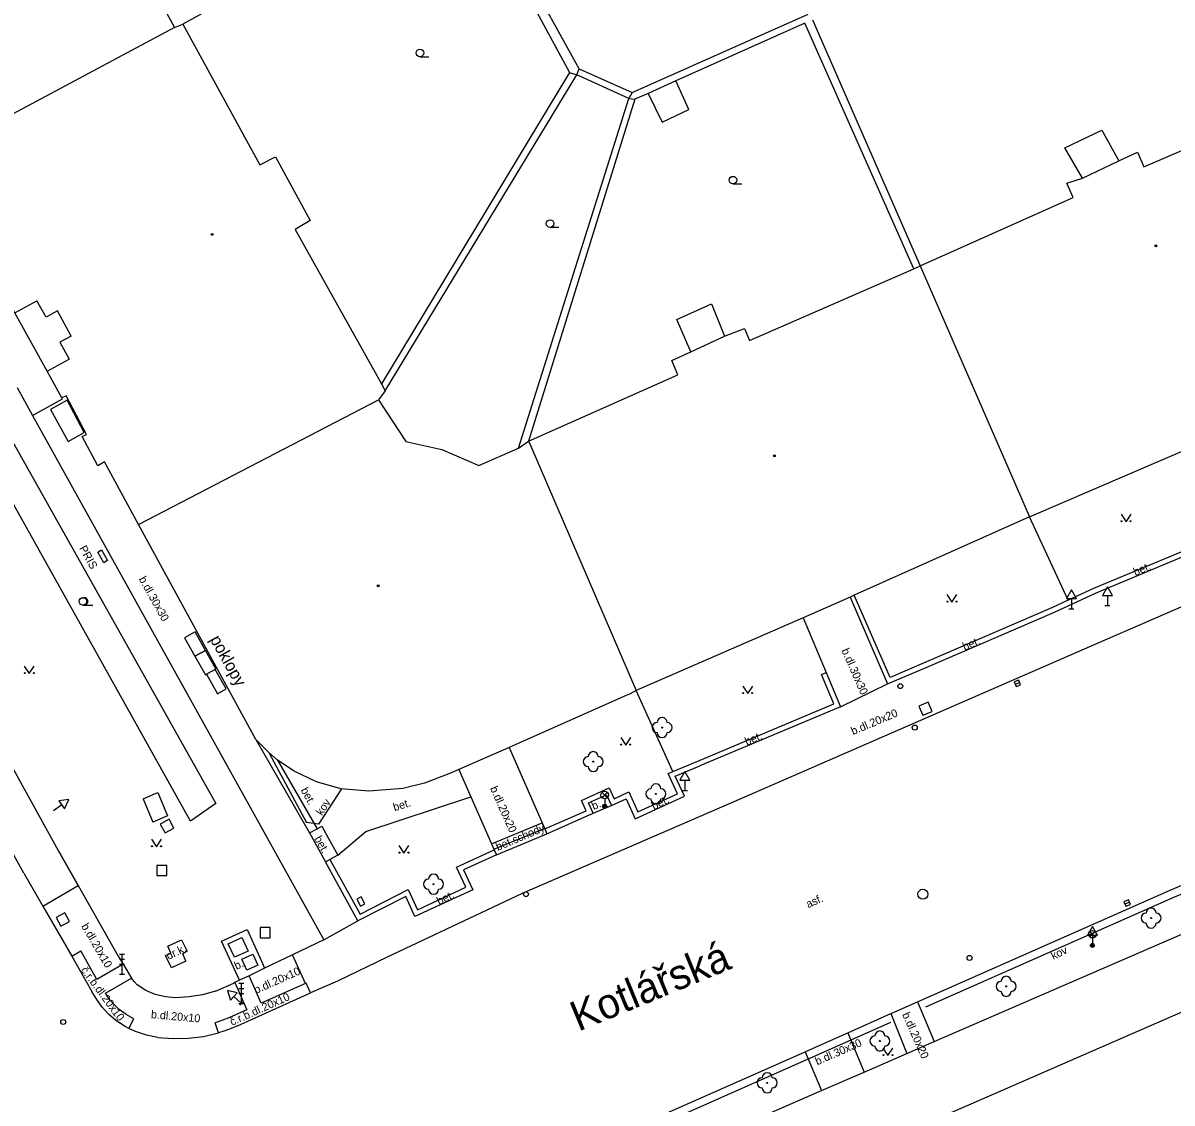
# Model space of a CAD drawing. Extents: x -599770 to -598493, y -1162076 to -1159209.
# Drawn here: x -598817.7 to -598760.3, y -1159496.4 to -1159442.5 of the extents above; entities that cross this region are included whole.
import ezdxf

# ---------------------------------------------------------------- set-up
doc = ezdxf.new("R2010")
doc.units = 0
doc.layers.add('Podklad', color=7, linetype='Continuous')

msp = doc.modelspace()

# ---------------------------------------------------------------- linework, layer by layer
at = {"layer": 'Podklad'}
for p, q in [((-598797.89, -1159444.157), (-598797.453, -1159444.157)), ((-598782.25, -1159450.508), (-598781.812, -1159450.508)), ((-598791.39, -1159452.677), (-598790.953, -1159452.677)), ((-598763.54, -1159471.061), (-598763.54, -1159471.57)), ((-598814.73, -1159471.547), (-598814.23, -1159471.547)), ((-598765.465, -1159471.73), (-598765.215, -1159471.73)), ((-598765.34, -1159471.221), (-598765.34, -1159471.73)), ((-598763.665, -1159471.57), (-598763.415, -1159471.57)), ((-598768.156, -1159475.497), (-598767.924, -1159475.403)), ((-598784.65, -1159480.291), (-598784.65, -1159480.8)), ((-598788.793, -1159481.16), (-598788.528, -1159480.895)), ((-598788.793, -1159480.895), (-598788.528, -1159481.16)), ((-598784.775, -1159480.8), (-598784.525, -1159480.8)), ((-598815.787, -1159481.512), (-598816.2, -1159481.81)), ((-598788.66, -1159481.215), (-598788.66, -1159481.59)), ((-598762.676, -1159486.467), (-598762.444, -1159486.373)), ((-598764.422, -1159488.11), (-598764.157, -1159487.845)), ((-598764.422, -1159487.845), (-598764.157, -1159488.11)), ((-598764.29, -1159488.031), (-598764.29, -1159488.54)), ((-598764.29, -1159488.165), (-598764.29, -1159488.54)), ((-598812.895, -1159488.98), (-598812.645, -1159488.98)), ((-598812.77, -1159489.98), (-598812.77, -1159488.98)), ((-598812.895, -1159489.23), (-598812.645, -1159489.23)), ((-598812.895, -1159489.48), (-598812.645, -1159489.48)), ((-598812.895, -1159489.98), (-598812.645, -1159489.98)), ((-598806.935, -1159490.43), (-598806.685, -1159490.43)), ((-598806.935, -1159490.68), (-598806.685, -1159490.68)), ((-598806.81, -1159491.43), (-598806.81, -1159490.43)), ((-598807.186, -1159491.087), (-598806.81, -1159491.43)), ((-598806.935, -1159490.93), (-598806.685, -1159490.93)), ((-598806.935, -1159491.43), (-598806.685, -1159491.43)), ((-598806.894, -1159491.522), (-598806.726, -1159491.338))]:
    msp.add_line(p, q, dxfattribs=at)
for points in [[(-598814.67, -1159434.41), (-598810.15, -1159442.7)], [(-598795.86, -1159434.88), (-598809.74, -1159442.53)], [(-598795.86, -1159434.88), (-598790.41, -1159444.94)], [(-598789.93, -1159444.76), (-598795.49, -1159434.69)], [(-598787.28, -1159445.95), (-598778.5, -1159442.03)], [(-598778.66, -1159442.49), (-598785.11, -1159445.37)], [(-598773.21, -1159454.75), (-598778.66, -1159442.49)], [(-598778.27, -1159442.32), (-598772.9, -1159454.6)], [(-598810.15, -1159442.7), (-598822.1, -1159449.08)], [(-598810.15, -1159442.7), (-598809.74, -1159442.53)], [(-598809.74, -1159442.53), (-598805.89, -1159449.56)], [(-598790.05, -1159445.07), (-598789.93, -1159444.76)], [(-598789.93, -1159444.76), (-598787.28, -1159445.95)], [(-598790.41, -1159444.94), (-598799.81, -1159460.5)], [(-598799.62, -1159460.84), (-598790.05, -1159445.07)], [(-598790.41, -1159444.94), (-598790.05, -1159445.07)], [(-598787.46, -1159446.25), (-598790.05, -1159445.07)], [(-598785.11, -1159445.37), (-598786.49, -1159445.99)], [(-598784.46, -1159446.79), (-598785.11, -1159445.37)], [(-598792.97, -1159463.7), (-598787.46, -1159446.25)], [(-598787.16, -1159446.27), (-598792.46, -1159463.36)], [(-598787.28, -1159445.95), (-598787.46, -1159446.25)], [(-598787.46, -1159446.25), (-598787.16, -1159446.27)], [(-598786.49, -1159445.99), (-598787.16, -1159446.27)], [(-598786.49, -1159445.99), (-598785.79, -1159447.43)], [(-598761.73, -1159449.65), (-598753.4, -1159446.07)], [(-598785.79, -1159447.43), (-598784.46, -1159446.79)], [(-598765.67, -1159448.71), (-598763.82, -1159447.83)], [(-598763.82, -1159447.83), (-598762.97, -1159449.36)], [(-598764.79, -1159450.22), (-598765.67, -1159448.71)], [(-598805.89, -1159449.56), (-598805.11, -1159449.16)], [(-598805.11, -1159449.16), (-598803.37, -1159452.34)], [(-598764.79, -1159450.22), (-598762.97, -1159449.36)], [(-598762.97, -1159449.36), (-598762.04, -1159448.92)], [(-598762.04, -1159448.92), (-598761.73, -1159449.65)], [(-598765.57, -1159450.47), (-598764.79, -1159450.22)], [(-598765.25, -1159451.19), (-598765.57, -1159450.47)], [(-598772.9, -1159454.6), (-598765.25, -1159451.19)], [(-598815.78, -1159461.19), (-598816.52, -1159459.86), (-598818.13, -1159456.94), (-598820.56, -1159452.53)], [(-598803.37, -1159452.34), (-598804.12, -1159452.78)], [(-598804.12, -1159452.78), (-598799.81, -1159460.5)], [(-598781.42, -1159458.33), (-598773.21, -1159454.75)], [(-598773.21, -1159454.75), (-598772.9, -1159454.6)], [(-598772.9, -1159454.6), (-598767.44, -1159467.14)], [(-598818.13, -1159456.94), (-598817.03, -1159456.34)], [(-598816.57, -1159457.17), (-598817.03, -1159456.34)], [(-598785.06, -1159457.28), (-598783.32, -1159456.5)], [(-598783.32, -1159456.5), (-598782.67, -1159458.11)], [(-598816, -1159456.85), (-598816.57, -1159457.17)], [(-598815.31, -1159458.11), (-598816, -1159456.85)], [(-598815.31, -1159458.11), (-598816, -1159456.85)], [(-598784.36, -1159458.9), (-598785.06, -1159457.28)], [(-598782.67, -1159458.11), (-598781.68, -1159457.73)], [(-598781.68, -1159457.73), (-598781.42, -1159458.33)], [(-598815.31, -1159458.11), (-598815.88, -1159458.42)], [(-598815.88, -1159458.42), (-598815.42, -1159459.26)], [(-598784.36, -1159458.9), (-598782.67, -1159458.11)], [(-598785.3, -1159459.32), (-598784.36, -1159458.9)], [(-598816.52, -1159459.86), (-598815.42, -1159459.26)], [(-598785, -1159460.04), (-598785.3, -1159459.32)], [(-598792.46, -1159463.36), (-598785, -1159460.04)], [(-598818.01, -1159460.68), (-598817.24, -1159462.08)], [(-598799.62, -1159460.84), (-598799.96, -1159461.3)], [(-598799.81, -1159460.5), (-598799.62, -1159460.84)], [(-598817.24, -1159462.08), (-598815.75, -1159461.25)], [(-598815.52, -1159461.31), (-598816.35, -1159461.77)], [(-598815.57, -1159461.09), (-598815.78, -1159461.19)], [(-598815.75, -1159461.25), (-598815.78, -1159461.19)], [(-598814.55, -1159463.03), (-598815.57, -1159461.09)], [(-598814.66, -1159462.92), (-598815.52, -1159461.31)], [(-598811.95, -1159467.52), (-598799.96, -1159461.3)], [(-598799.96, -1159461.3), (-598798.6, -1159463.38)], [(-598816.35, -1159461.77), (-598815.47, -1159463.37)], [(-598817.68, -1159484.93), (-598828.62, -1159465.24), (-598830.4, -1159462.04)], [(-598809.35, -1159482.34), (-598820.19, -1159462.95), (-598818.87, -1159462.27), (-598808.08, -1159481.45), (-598809.35, -1159482.34)], [(-598817.24, -1159462.08), (-598802.69, -1159488.26)], [(-598815.47, -1159463.37), (-598814.66, -1159462.92)], [(-598814.76, -1159463.12), (-598814.55, -1159463.03)], [(-598813.99, -1159464.58), (-598814.76, -1159463.12)], [(-598798.6, -1159463.38), (-598796.8, -1159463.78)], [(-598794.95, -1159464.57), (-598792.97, -1159463.7)], [(-598792.97, -1159463.7), (-598792.46, -1159463.36)], [(-598792.46, -1159463.36), (-598792.35, -1159463.61)], [(-598792.35, -1159463.61), (-598787.08, -1159475.81)], [(-598767.44, -1159467.14), (-598759.34, -1159463.66), (-598759.11, -1159463.56)], [(-598796.8, -1159463.78), (-598794.95, -1159464.57)], [(-598813.65, -1159464.39), (-598813.99, -1159464.58)], [(-598811.95, -1159467.52), (-598813.65, -1159464.39)], [(-598814.97, -1159485.54), (-598815.95, -1159483.82), (-598826.26, -1159465.16)], [(-598748.87, -1159466.87), (-598764.43, -1159473.63), (-598781.83, -1159481.2), (-598792.78, -1159485.95)], [(-598767.44, -1159467.14), (-598776.19, -1159471.05), (-598776.39, -1159471.14)], [(-598765.5, -1159471.3), (-598767.44, -1159467.14)], [(-598762.86, -1159467.005), (-598762.61, -1159467.38), (-598762.36, -1159467.005)], [(-598806.09, -1159478.25), (-598811.95, -1159467.52)], [(-598776.39, -1159471.14), (-598774.53, -1159475.48), (-598772.59, -1159474.66), (-598766.18, -1159471.9), (-598764.14, -1159470.94), (-598757.18, -1159468.04)], [(-598757.51, -1159467.91), (-598764.24, -1159470.71), (-598765.5, -1159471.3), (-598766.28, -1159471.67), (-598772.69, -1159474.43), (-598774.4, -1159475.15), (-598776.19, -1159471.05)], [(-598813.8, -1159468.79), (-598813.5, -1159469.32), (-598813.69, -1159469.43), (-598813.99, -1159468.9), (-598813.8, -1159468.79)], [(-598776.39, -1159471.14), (-598778.74, -1159472.18)], [(-598771.56, -1159471.015), (-598771.31, -1159471.39), (-598771.06, -1159471.015)], [(-598778.74, -1159472.18), (-598787.08, -1159475.81)], [(-598778.74, -1159472.18), (-598777.6, -1159474.9)], [(-598809.12, -1159472.88), (-598809.65, -1159473.17)], [(-598808.6, -1159473.81), (-598809.12, -1159472.88)], [(-598809.65, -1159473.17), (-598809.13, -1159474.1)], [(-598808.6, -1159473.81), (-598809.13, -1159474.1)], [(-598809.13, -1159474.1), (-598808.6, -1159473.81)], [(-598808.09, -1159474.73), (-598808.6, -1159473.81)], [(-598817.659, -1159474.59), (-598817.409, -1159474.965), (-598817.159, -1159474.59)], [(-598809.13, -1159474.1), (-598808.61, -1159475.02)], [(-598808.61, -1159475.02), (-598808.56, -1159474.99), (-598808.09, -1159474.73)], [(-598808.12, -1159474.75), (-598808.56, -1159474.99)], [(-598808.56, -1159474.99), (-598808.01, -1159475.97)], [(-598807.57, -1159475.73), (-598808.12, -1159474.75)], [(-598777.6, -1159474.9), (-598776.88, -1159476.62), (-598783.91, -1159479.57)], [(-598777.21, -1159476.48), (-598777.83, -1159475), (-598777.6, -1159474.9)], [(-598808.01, -1159475.97), (-598807.57, -1159475.73)], [(-598781.76, -1159475.585), (-598781.51, -1159475.96), (-598781.26, -1159475.585)], [(-598776.88, -1159476.62), (-598774.53, -1159475.48)], [(-598787.7, -1159476.11), (-598793.44, -1159478.65)], [(-598787.39, -1159475.97), (-598787.7, -1159476.11)], [(-598787.08, -1159475.81), (-598787.39, -1159475.97)], [(-598785.25, -1159479.85), (-598787.08, -1159475.81)], [(-598784.01, -1159479.33), (-598777.21, -1159476.48)], [(-598805, -1159479.29), (-598805.44, -1159478.91), (-598806.09, -1159478.25)], [(-598806.09, -1159478.25), (-598803.41, -1159482.92)], [(-598793.44, -1159478.65), (-598795.95, -1159479.76)], [(-598793.44, -1159478.65), (-598791.79, -1159482.41), (-598791.65, -1159482.72)], [(-598787.86, -1159478.155), (-598787.61, -1159478.53), (-598787.36, -1159478.155)], [(-598805.43, -1159478.93), (-598803.55, -1159482.4)], [(-598801.85, -1159480.71), (-598803.05, -1159480.37), (-598804.18, -1159479.84), (-598805, -1159479.29)], [(-598805, -1159479.29), (-598803.03, -1159482.71)], [(-598795.95, -1159479.76), (-598796.36, -1159479.93)], [(-598795.95, -1159479.76), (-598795.35, -1159481.11)], [(-598791.65, -1159482.72), (-598791.55, -1159482.96), (-598789.23, -1159481.94), (-598789.47, -1159481.42), (-598788.57, -1159481.01), (-598788.32, -1159481.55), (-598787.59, -1159481.22), (-598787.13, -1159482.22), (-598784.68, -1159481.09), (-598785.14, -1159480.09), (-598783.91, -1159479.57)], [(-598785.03, -1159480.96), (-598785.49, -1159479.95), (-598785.25, -1159479.85), (-598784.01, -1159479.33)], [(-598796.36, -1159479.93), (-598797.67, -1159480.44), (-598798.74, -1159480.7)], [(-598760.41, -1159485.78), (-598748.8, -1159480.8), (-598747.8, -1159480.37)], [(-598811.72, -1159481.21), (-598810.98, -1159480.9), (-598810.5, -1159482.07), (-598811.23, -1159482.38)], [(-598801.81, -1159480.72), (-598802.95, -1159482.48), (-598803.55, -1159482.4)], [(-598798.74, -1159480.7), (-598800.45, -1159480.84), (-598801.85, -1159480.71)], [(-598789.58, -1159481.81), (-598789.82, -1159481.3), (-598788.44, -1159480.66)], [(-598788.44, -1159480.66), (-598788.19, -1159481.21)], [(-598788.19, -1159481.21), (-598787.46, -1159480.87), (-598787, -1159481.87), (-598785.03, -1159480.96)], [(-598811.72, -1159481.21), (-598811.23, -1159482.38)], [(-598802, -1159484.03), (-598800.6, -1159482.84), (-598795.35, -1159481.11)], [(-598795.35, -1159481.11), (-598794.32, -1159483.46), (-598794.18, -1159483.77)], [(-598791.65, -1159482.72), (-598789.58, -1159481.81)], [(-598789.23, -1159481.94), (-598788.32, -1159481.55)], [(-598772.61, -1159491.6), (-598760.25, -1159486.14), (-598749.35, -1159481.61)], [(-598803.409, -1159482.92), (-598803.03, -1159482.71), (-598802.796, -1159482.583), (-598802.472, -1159483.172), (-598802, -1159484.029), (-598802.39, -1159484.25)], [(-598794.32, -1159483.46), (-598791.79, -1159482.41)], [(-598811.302, -1159483.234), (-598811.052, -1159483.609), (-598810.802, -1159483.234)], [(-598803.41, -1159482.92), (-598802.61, -1159484.37)], [(-598794.19, -1159483.73), (-598791.67, -1159482.69)], [(-598794.07, -1159484.01), (-598791.55, -1159482.96)], [(-598815.95, -1159483.82), (-598814.97, -1159485.54), (-598812.96, -1159489.08)], [(-598794.18, -1159483.77), (-598794.07, -1159484.01), (-598795.71, -1159484.76), (-598795.25, -1159485.76), (-598798.14, -1159487.1), (-598798.6, -1159486.1), (-598800.99, -1159487.31), (-598802.61, -1159484.37), (-598802.39, -1159484.25)], [(-598800.88, -1159486.97), (-598798.48, -1159485.75), (-598798.01, -1159486.76), (-598795.59, -1159485.63), (-598796.06, -1159484.63), (-598794.18, -1159483.77)], [(-598798.94, -1159483.555), (-598798.69, -1159483.93), (-598798.44, -1159483.555)], [(-598802.39, -1159484.25), (-598800.88, -1159486.97)], [(-598817.68, -1159484.93), (-598816.73, -1159486.57), (-598815.29, -1159489.08), (-598814.28, -1159490.83)], [(-598816.73, -1159486.57), (-598814.97, -1159485.54)], [(-598792.78, -1159485.95), (-598799.53, -1159489.12), (-598802.01, -1159490.32), (-598803.35, -1159490.91)], [(-598800.83, -1159486.11), (-598801.04, -1159486.22)], [(-598800.65, -1159486.46), (-598800.83, -1159486.11)], [(-598786.25, -1159497.21), (-598778.64, -1159493.85), (-598778.58, -1159493.82), (-598776.52, -1159492.9), (-598774.36, -1159491.94), (-598774.05, -1159491.8), (-598773.03, -1159491.35), (-598760.41, -1159485.78)], [(-598801.04, -1159486.22), (-598800.86, -1159486.57)], [(-598800.86, -1159486.57), (-598800.65, -1159486.46)], [(-598806.91, -1159490.28), (-598807.8, -1159488.32), (-598806.52, -1159487.74), (-598805.8, -1159489.33)], [(-598802.69, -1159488.26), (-598800.99, -1159487.31)], [(-598772.2, -1159493.34), (-598758.82, -1159487.54)], [(-598809.58, -1159489.33), (-598810.31, -1159489.65), (-598810.6, -1159489.04), (-598810.34, -1159488.92), (-598810.49, -1159488.58), (-598809.8, -1159488.25), (-598809.52, -1159488.83), (-598809.74, -1159488.96)], [(-598807.47, -1159488.45), (-598806.78, -1159488.14), (-598806.47, -1159488.82), (-598807.15, -1159489.13), (-598807.47, -1159488.45)], [(-598802.69, -1159488.26), (-598804.25, -1159489.01), (-598805.65, -1159489.68), (-598806.42, -1159490.05), (-598806.91, -1159490.28), (-598807.13, -1159490.39), (-598807.19, -1159490.42)], [(-598815.29, -1159489.08), (-598814.83, -1159488.81)], [(-598814.03, -1159490.24), (-598814.83, -1159488.81)], [(-598809.58, -1159489.33), (-598809.74, -1159488.96)], [(-598806.79, -1159489.22), (-598806.24, -1159488.97), (-598805.99, -1159489.52), (-598806.54, -1159489.77), (-598806.79, -1159489.22)], [(-598775.39, -1159498.63), (-598772.46, -1159497.36), (-598770.73, -1159496.61), (-598753.25, -1159488.99)], [(-598812.71, -1159489.48), (-598814.03, -1159490.24)], [(-598812.96, -1159489.08), (-598812.71, -1159489.48), (-598812.3, -1159490.17)], [(-598805.8, -1159489.33), (-598805.65, -1159489.68)], [(-598803.61, -1159490.44), (-598804.25, -1159489.01)], [(-598803.57, -1159490.42), (-598803.61, -1159490.44), (-598805.83, -1159491.42), (-598806.42, -1159490.05)], [(-598813.6, -1159490.92), (-598812.3, -1159490.17)], [(-598812.01, -1159490.51), (-598812.17, -1159490.34), (-598812.3, -1159490.17)], [(-598809.42, -1159491.11), (-598810.1, -1159491.15), (-598810.61, -1159491.11), (-598811.11, -1159490.99), (-598811.58, -1159490.79), (-598812.01, -1159490.51)], [(-598808.1, -1159490.82), (-598807.19, -1159490.42)], [(-598807.13, -1159490.39), (-598806.54, -1159491.76), (-598807.1, -1159492.01)], [(-598803.35, -1159490.91), (-598803.57, -1159490.42)], [(-598813.09, -1159492.28), (-598813.45, -1159491.97), (-598813.77, -1159491.62), (-598814.04, -1159491.24), (-598814.28, -1159490.83)], [(-598813.22, -1159491.44), (-598813.36, -1159491.27), (-598813.49, -1159491.1), (-598813.6, -1159490.92)], [(-598808.1, -1159490.82), (-598808.75, -1159491), (-598809.42, -1159491.11)], [(-598807.01, -1159492.56), (-598803.35, -1159490.91)], [(-598812.19, -1159492.2), (-598812.57, -1159491.99), (-598812.91, -1159491.74), (-598813.22, -1159491.44)], [(-598773.03, -1159491.35), (-598772.2, -1159493.34)], [(-598810.98, -1159493.13), (-598811.55, -1159493.02), (-598812.1, -1159492.84), (-598812.43, -1159492.68), (-598812.61, -1159492.59), (-598813.09, -1159492.28)], [(-598812.43, -1159492.68), (-598812.19, -1159492.2)], [(-598807.1, -1159492.01), (-598807.44, -1159492.15), (-598807.78, -1159492.28), (-598808.12, -1159492.41)], [(-598807.96, -1159492.91), (-598808.12, -1159492.41)], [(-598774.38, -1159492.38), (-598776.36, -1159493.27), (-598778.42, -1159494.19), (-598786.09, -1159497.58)], [(-598774.36, -1159491.94), (-598773.56, -1159493.93)], [(-598810.98, -1159493.13), (-598810.22, -1159493.19), (-598809.46, -1159493.17), (-598808.7, -1159493.08), (-598807.96, -1159492.91)], [(-598807.01, -1159492.56), (-598807.32, -1159492.69), (-598807.63, -1159492.81), (-598807.96, -1159492.91)], [(-598776.52, -1159492.9), (-598775.7, -1159494.86)], [(-598773.56, -1159493.93), (-598772.2, -1159493.34)], [(-598778.64, -1159493.85), (-598777.82, -1159495.78)], [(-598775.7, -1159494.86), (-598773.56, -1159493.93)], [(-598774.76, -1159493.665), (-598774.51, -1159494.04), (-598774.26, -1159493.665)], [(-598777.82, -1159495.78), (-598775.7, -1159494.86)], [(-598796.99, -1159504.16), (-598777.82, -1159495.78)]]:
    msp.add_lwpolyline(points, dxfattribs=at)
for points in [[(-598765.59, -1159471.221), (-598765.09, -1159471.221), (-598765.34, -1159470.788)], [(-598763.79, -1159471.061), (-598763.29, -1159471.061), (-598763.54, -1159470.628)], [(-598768.108, -1159475.613), (-598767.877, -1159475.518), (-598767.972, -1159475.287), (-598768.203, -1159475.382)], [(-598772.496, -1159476.393), (-598772.957, -1159476.586), (-598772.764, -1159477.047), (-598772.303, -1159476.854)], [(-598784.9, -1159480.291), (-598784.4, -1159480.291), (-598784.65, -1159479.858)], [(-598815.934, -1159481.309), (-598815.641, -1159481.714), (-598815.437, -1159481.258)], [(-598810.179, -1159482.675), (-598810.425, -1159482.239), (-598810.861, -1159482.485), (-598810.615, -1159482.921)], [(-598811.03, -1159485.05), (-598810.53, -1159485.05), (-598810.53, -1159484.55), (-598811.03, -1159484.55)], [(-598762.628, -1159486.583), (-598762.397, -1159486.488), (-598762.492, -1159486.257), (-598762.723, -1159486.352)], [(-598816.068, -1159487.137), (-598815.833, -1159487.578), (-598815.392, -1159487.343), (-598815.627, -1159486.902)], [(-598805.87, -1159488.15), (-598805.37, -1159488.15), (-598805.37, -1159487.65), (-598805.87, -1159487.65)], [(-598764.54, -1159488.031), (-598764.04, -1159488.031), (-598764.29, -1159487.598)], [(-598807.355, -1159491.272), (-598807.018, -1159490.903), (-598807.507, -1159490.796)]]:
    msp.add_lwpolyline(points, close=True, dxfattribs=at)
for centre, radius in [((-598797.89, -1159443.97), 0.188), ((-598782.25, -1159450.32), 0.188), ((-598791.39, -1159452.49), 0.188), ((-598808.27, -1159453.03), 0.045), ((-598808.27, -1159453.03), 0.0199), ((-598761.12, -1159453.6), 0.045), ((-598761.12, -1159453.6), 0.0199), ((-598780.18, -1159464.09), 0.045), ((-598780.18, -1159464.09), 0.0199), ((-598762.835, -1159467.355), 0.025), ((-598762.385, -1159467.355), 0.025), ((-598799.98, -1159470.58), 0.045), ((-598799.98, -1159470.58), 0.0199), ((-598814.73, -1159471.36), 0.188), ((-598771.535, -1159471.365), 0.025), ((-598771.085, -1159471.365), 0.025), ((-598817.634, -1159474.939), 0.025), ((-598817.185, -1159474.939), 0.025), ((-598773.89, -1159475.59), 0.125), ((-598781.735, -1159475.935), 0.025), ((-598781.285, -1159475.935), 0.025), ((-598785.79, -1159477.66), 0.025), ((-598773.17, -1159477.66), 0.125), ((-598787.835, -1159478.505), 0.025), ((-598787.385, -1159478.505), 0.025), ((-598789.23, -1159479.36), 0.025), ((-598788.66, -1159481.027), 0.188), ((-598786.1, -1159480.97), 0.025), ((-598788.66, -1159481.59), 0.1), ((-598788.66, -1159481.59), 0.0723), ((-598788.66, -1159481.59), 0.0438), ((-598811.277, -1159483.584), 0.025), ((-598810.827, -1159483.584), 0.025), ((-598798.915, -1159483.905), 0.025), ((-598798.465, -1159483.905), 0.025), ((-598797.21, -1159485.48), 0.025), ((-598792.59, -1159485.98), 0.125), ((-598772.76, -1159485.98), 0.25), ((-598761.36, -1159487.17), 0.025), ((-598764.29, -1159487.977), 0.188), ((-598764.29, -1159488.54), 0.1), ((-598764.29, -1159488.54), 0.0723), ((-598764.29, -1159488.54), 0.0438), ((-598770.43, -1159489.16), 0.125), ((-598768.6, -1159490.58), 0.025), ((-598815.71, -1159492.36), 0.125), ((-598774.91, -1159493.31), 0.025), ((-598774.735, -1159494.015), 0.025), ((-598774.285, -1159494.015), 0.025), ((-598780.54, -1159495.4), 0.025)]:
    msp.add_circle(centre, radius, dxfattribs=at)
for centre, radius, start, end in [((-598814.668, -1159471.36), 0.188, 260.40593, 99.59407), ((-598786.04, -1159477.66), 0.25, 90, 270), ((-598785.79, -1159477.41), 0.25, 0, 180), ((-598785.54, -1159477.66), 0.25, 270, 90), ((-598785.79, -1159477.91), 0.25, 180, 0), ((-598789.48, -1159479.36), 0.25, 90, 270), ((-598789.23, -1159479.11), 0.25, 0, 180), ((-598788.98, -1159479.36), 0.25, 270, 90), ((-598789.23, -1159479.61), 0.25, 180, 0), ((-598786.35, -1159480.97), 0.25, 90, 270), ((-598786.1, -1159480.72), 0.25, 0, 180), ((-598785.85, -1159480.97), 0.25, 270, 90), ((-598786.1, -1159481.22), 0.25, 180, 0), ((-598797.46, -1159485.48), 0.25, 90, 270), ((-598797.21, -1159485.23), 0.25, 0, 180), ((-598796.96, -1159485.48), 0.25, 270, 90), ((-598797.21, -1159485.73), 0.25, 180, 0), ((-598761.36, -1159486.92), 0.25, 0, 180), ((-598761.61, -1159487.17), 0.25, 90, 270), ((-598761.11, -1159487.17), 0.25, 270, 90), ((-598761.36, -1159487.42), 0.25, 180, 0), ((-598768.6, -1159490.33), 0.25, 0, 180), ((-598768.85, -1159490.58), 0.25, 90, 270), ((-598768.35, -1159490.58), 0.25, 270, 90), ((-598768.6, -1159490.83), 0.25, 180, 0), ((-598774.91, -1159493.06), 0.25, 0, 180), ((-598775.16, -1159493.31), 0.25, 90, 270), ((-598774.91, -1159493.56), 0.25, 180, 0), ((-598774.66, -1159493.31), 0.25, 270, 90), ((-598780.79, -1159495.4), 0.25, 90, 270), ((-598780.54, -1159495.15), 0.25, 0, 180), ((-598780.29, -1159495.4), 0.25, 270, 90), ((-598780.54, -1159495.65), 0.25, 180, 0)]:
    msp.add_arc(centre, radius, start, end, dxfattribs=at)

# ---------------------------------------------------------------- texts
for s, height, rotation, p in [('PRIS', 0.4, 299, (-598814.93, -1159468.7)), ('bet.', 0.4, 22.41043, (-598762.15, -1159470.09)), ('b.dl.30x30', 0.4, 299.0821, (-598811.95, -1159470.24)), ('poklopy', 0.6, 299.22524, (-598808.4, -1159473.25)), ('bet.', 0.4, 22.41043, (-598770.68, -1159473.82)), ('b.dl.30x30', 0.4, 293.65, (-598776.84, -1159473.8)), ('b.dl.20x20', 0.4, 23, (-598776.25, -1159478.04)), ('bet.', 0.4, 22.41043, (-598781.56, -1159478.56)), ('bet.', 0.4, 298.83208, (-598803.86, -1159480.78)), ('bet.', 0.4, 298.83208, (-598803.86, -1159480.78)), ('b.dl.20x20', 0.4, 294, (-598794.4, -1159480.69)), ('kov', 0.4, 56.95439, (-598802.78, -1159482.08)), ('kov', 0.4, 56.95439, (-598802.78, -1159482.08)), ('bet.', 0.4, 17.33933, (-598799.16, -1159481.84)), ('b.', 0.4, 24, (-598789.21, -1159481.78)), ('bet.', 0.4, 26.13183, (-598786.2, -1159481.78)), ('bet.schody', 0.4, 23, (-598793.998, -1159483.82)), ('bet.', 0.4, 298.83208, (-598803.18, -1159483.2)), ('bet.', 0.4, 26.13183, (-598796.93, -1159486.53)), ('asf.', 0.4, 24, (-598778.49, -1159486.68)), ('b.dl.20x10', 0.4, 300.28493, (-598814.824, -1159487.572)), ('Kotlářská', 1.5, 22.36, (-598789.98, -1159492.85)), ('dr.k.', 0.4, 26, (-598810.447, -1159489.267)), ('kov', 0.4, 25.43969, (-598766.25, -1159489.26)), ('b.', 0.4, 24, (-598807.06, -1159489.76)), ('č.r.b.dl.20x10', 0.4, 306.68651, (-598814.857, -1159489.78)), ('b.dl.20x10', 0.4, 24, (-598806.078, -1159490.964)), ('č.r.b.dl.20x10', 0.4, 24.24, (-598807.28, -1159492.56)), ('b.dl.20x10', 0.4, 355, (-598811.34, -1159492.17)), ('b.dl.20x20', 0.4, 293.91, (-598773.81, -1159491.98)), ('b.dl.30x30', 0.4, 23.57, (-598778.04, -1159494.53))]:
    msp.add_text(s, height=height, rotation=rotation, dxfattribs=at).set_placement(p)

doc.saveas('drawing.dxf')
